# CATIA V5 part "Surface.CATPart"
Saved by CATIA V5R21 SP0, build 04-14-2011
Part number: Part1
Bounding box of the stored display mesh (mm): x -50 to 50, y 0 to 200, z 0 to 79.597
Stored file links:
  D:\CATIA V5R21 E-RESOURCES\CATIA-V5R21\catia-v5r21-prt\c16-catia-v5r20-prt\Point Surface Joint-(Fig16-46)\CAT_V5R21_Surface.CATPart
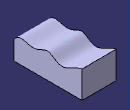
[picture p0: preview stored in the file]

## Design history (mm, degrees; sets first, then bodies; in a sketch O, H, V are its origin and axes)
Body1 (main body)
  Sketch1 on yz-plane, origin (0, 0, 0), H (0, 1, 0), V (0, 0, 1)
    spline S1 through (0, 52.7587) (16.6889, 67.1156) (74.2459, 65.3633) (97.6382, 74.1545) (129.8025, 59.0839) (168.2327, 66.2006) (200, 79.5967)
    line L1 (0, 52.7587) -> (0, 0)
    point P1 (0, 52.7587)
    point P2 (0, 0)
    line L2 (0, 0) -> (200, 0)
    line L3 (200, 0) -> (200, 79.5967)
    point P4 (200, 79.5967)
    point P5 (0, 52.7587)
    point P6 (200, 79.5967)
    length L2 = 200
    coincidence: P5 P1, P2 H, P6 P4, L1 V
    vertical: L1 V, L3 V
    horizontal: L2 H
  Pad1: profile Sketch1, direction (1, 0, 0), length 50, mirrored extent
  Point1: type OnSurface, Support face of Pad1 from Sketch1.S1, Length 0, Direction (0.8882, 0.2225, -0.4019)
